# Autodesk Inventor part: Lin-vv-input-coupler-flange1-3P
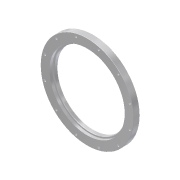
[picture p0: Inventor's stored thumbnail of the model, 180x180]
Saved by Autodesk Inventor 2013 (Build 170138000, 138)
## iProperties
Created: 2012-05
Part Number: Lin-vv-input-coupler-flange1-3P
Material: Stainless Steel, 316
Description: INPUT COUPLER FLANGE
Document SubType Name: Modeling
Designer: Henneborn
Manufacturer: Standard
Standards Organization: Custom
Density: 7.9 g/cm^3
Rohmasse: 13,3" O.D  x 0,88" made of sheet
Author: vm
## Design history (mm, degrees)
sketch "Sketch1"
  geometry: C1 r 168.91 at (0, 0); C2 r 130.175 at (0, 0); 1 further point
  constraints: 2 centre point, 1 coincident
  dimensions: "d0" = 337.82 diameter of C1; "d1" = 260.35 diameter of C2
extrude "Extrusion1" new body sketch "Sketch1" stored distance "d2" = 22.225; taper "d3" = 0 deg
sketch "Sketch2"
  geometry: C1 r 130.175 at (0, 0) reference; C2 r 136.525 at (0, 0)
  constraints: 1 centre point
  dimensions: "d4" = 273.05 diameter of C2
extrude "Extrusion2" cut sketch "Sketch2" distance "d5" = 10.16; taper "d6" = 0 deg
chamfer "Chamfer1" distance "d7" = 1.5875; stored, may be unused: second distance "d8" = 3.175, angle "d9" = 45 deg
sketch "Sketch3"
  geometry: L1 (0, 0)-(-41.088, 153.341); L2 (0, -202.692)-(0, 270.256) reference; C1 r 168.91 at (0, 0) reference; 1 further point
  constraints: 2 end point, 1 coincident
  dimensions: "d10" = 15 deg angle of L2 L1; "d11" = 158.75 distance of L1.start L1.end
hole "Hole1" sketch "Sketch3" at (-41.088, 153.341) diameter "d12" = 8.7376; stored, may be unused: countersink angle "d16" = 82 deg, drill point angle "d18" = 118 deg; dims "d13" = 12.7, "d14" = 9.525, "d15" = 6.35, "d17" = 19.05
pattern_circular "Circular Pattern1" dims angle "d21" = 360 deg
workaxis "Work Axis1"
workaxis "Work Axis2"
workplane "Work Plane1"
chamfer "Chamfer3" distance "d25" = 0.79375; stored, may be unused: second distance "d26" = 3.175, angle "d27" = 45 deg
body "Solid1"
